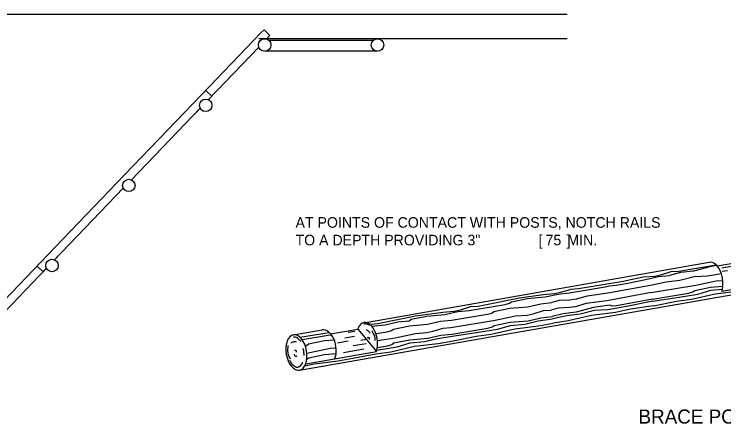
# Model space of a CAD drawing. Extents: x 49991 to 50288, y 49919 to 50011.
# Drawn here: x 50102.33 to 50131.11, y 49960.39 to 49977 of the extents above; entities that cross this region are included whole.
import ezdxf

# ---------------------------------------------------------------- set-up
doc = ezdxf.new("R2010")
doc.units = 0
for name, color, linetype in [('Level 1', 7, 'Continuous'), ('Level 2', 7, 'Continuous'), ('Level 7', 7, 'Continuous')]:
    doc.layers.add(name, color=color, linetype=linetype)

msp = doc.modelspace()

# ---------------------------------------------------------------- linework, layer by layer
at = {"layer": 'Level 1'}
for p, q in [((50059.75292181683, 49976.99558000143), (50124.75625647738, 49976.99558000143)), ((50124.75625647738, 49975.99557998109), (50112.25625622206, 49975.99557998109)), ((50112.25625622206, 49975.99557998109), (50112.25625622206, 49975.99557998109)), ((50116.90350931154, 49975.93557997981), (50112.660963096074, 49975.93557997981)), ((50117.06883965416, 49975.494707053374), (50112.49308956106, 49975.49695705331)), ((50113.90505239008, 49962.567250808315), (50149.87663416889, 49968.84808164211)), ((50116.520059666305, 49964.49143184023), (50130.523789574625, 49966.93785282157)), ((50131.954379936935, 49966.97514372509), (50130.84970517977, 49966.78227097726)), ((50131.96889181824, 49966.86947742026), (50131.02839103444, 49966.70487244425)), ((50131.26102300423, 49966.59721857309), (50131.05133796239, 49966.56090967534)), ((50131.02828853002, 49965.77066362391), (50132.712934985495, 49966.06495613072)), ((50113.663257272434, 49963.995649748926), (50114.82930681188, 49964.199365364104)), ((50115.16749844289, 49964.04250308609), (50116.2666037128, 49964.23451505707)), ((50115.883282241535, 49964.100603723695), (50116.1527901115, 49964.148121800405)), ((50116.2666037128, 49964.23451505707), (50117.02629303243, 49963.32762575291)), ((50115.74198177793, 49963.87829686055), (50116.13803925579, 49963.94777193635)), ((50115.4423207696, 49963.67660187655), (50115.87895074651, 49963.752878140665)), ((50116.076290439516, 49963.56094801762), (50116.604017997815, 49963.65315100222)), ((50116.39043230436, 49963.78782972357), (50116.60856542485, 49963.82629257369)), ((50114.15968473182, 49962.826833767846), (50117.026293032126, 49963.32762575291)), ((50115.691358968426, 49963.28703951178), (50116.51805030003, 49963.43219941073))]:
    msp.add_line(p, q, dxfattribs=at)
for points in [[(50130.8272706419, 49966.807120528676), (50130.59782333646, 49966.77442249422), (50129.88999318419, 49966.58445958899), (50129.35730476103, 49966.51939833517), (50128.9160325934, 49966.409742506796)], [(50129.28732143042, 49966.58514272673), (50130.799775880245, 49966.83498333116)], [(50125.22073166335, 49965.87554302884), (50127.028379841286, 49966.17369169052), (50127.85023236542, 49966.34482402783), (50128.31721149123, 49966.38033114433), (50128.564988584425, 49966.43220022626), (50128.984814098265, 49966.56160314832), (50129.28732143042, 49966.58514272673)], [(50131.01458391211, 49966.47797358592), (50130.45543829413, 49966.37421677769), (50129.90699049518, 49966.344626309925), (50129.335264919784, 49966.19605751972), (50128.782820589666, 49966.127752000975), (50128.20787660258, 49966.01454465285)], [(50124.848838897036, 49965.6991341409), (50126.30784767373, 49965.940086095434), (50126.48360027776, 49965.988928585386), (50126.754183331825, 49966.00861599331), (50127.21653904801, 49966.0930268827), (50127.9397412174, 49966.24376557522), (50128.46297562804, 49966.36315911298), (50128.9160325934, 49966.409742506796)], [(50128.172146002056, 49965.71365178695), (50129.979745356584, 49966.01226816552), (50130.80271834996, 49966.18399027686), (50131.073420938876, 49966.20420989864)], [(50121.1535623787, 49965.164700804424), (50122.823639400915, 49965.49281741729), (50123.78392527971, 49965.63478102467), (50124.25046110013, 49965.67000545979), (50124.49844764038, 49965.72213281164), (50124.91731330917, 49965.85167194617), (50125.22073166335, 49965.87554302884)], [(50128.20787660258, 49966.01454465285), (50126.40589722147, 49965.682472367), (50125.57276864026, 49965.56500930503), (50125.12318792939, 49965.439828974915), (50124.87212800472, 49965.405820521), (50124.43393541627, 49965.38442941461), (50124.14112621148, 49965.304218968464)], [(50128.21819159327, 49965.44919115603), (50129.67683029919, 49965.68915885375), (50129.85258290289, 49965.73800134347), (50129.934602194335, 49965.79928164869), (50130.57850754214, 49965.93127149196), (50131.0735271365, 49965.97332495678)], [(50128.26501835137, 49965.177247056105), (50129.19945831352, 49965.36367799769), (50129.8097608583, 49965.44842497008), (50130.769358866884, 49965.665614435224), (50131.7343230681, 49965.783836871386), (50132.33078448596, 49965.88794281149)], [(50120.781620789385, 49964.988759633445), (50122.24083901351, 49965.229969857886), (50122.41661602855, 49965.278578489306), (50122.49868414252, 49965.33939107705), (50123.14191232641, 49965.47107382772), (50123.872805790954, 49965.532947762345), (50124.3965079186, 49965.65239012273), (50124.848838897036, 49965.6991341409)], [(50128.172146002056, 49965.71365178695), (50126.36998158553, 49965.38108737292), (50125.53729630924, 49965.26390699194), (50125.0874573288, 49965.13893610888), (50124.83618795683, 49965.10466938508), (50124.39862370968, 49965.08405308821), (50124.10570270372, 49965.002648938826)], [(50128.23330024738, 49965.35880611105), (50129.30546187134, 49965.5213153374), (50130.063854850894, 49965.645870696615), (50130.59059366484, 49965.80416432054), (50131.051502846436, 49965.84652030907)], [(50120.07423960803, 49964.59293343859), (50121.532707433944, 49964.83453814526), (50121.7092348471, 49964.8827522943), (50121.790528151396, 49964.94419322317), (50122.43474059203, 49965.07550590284), (50123.165166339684, 49965.1373310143), (50123.6886101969, 49965.2569828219), (50124.14112621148, 49965.304218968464)], [(50128.21819159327, 49965.44919115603), (50126.76421691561, 49965.18039589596), (50126.581947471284, 49965.16680694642), (50126.484955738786, 49965.19687153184), (50125.83405557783, 49965.10244940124), (50125.12645928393, 49964.912510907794), (50124.593278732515, 49964.847634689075), (50124.15219160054, 49964.73847098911)], [(50128.23330024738, 49965.35880611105), (50127.17102958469, 49965.149102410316), (50126.415256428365, 49965.008508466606), (50125.86634091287, 49964.97886917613), (50125.29513187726, 49964.82988149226), (50124.74191273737, 49964.76220431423), (50124.167743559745, 49964.64836862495)], [(50117.086344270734, 49964.45432629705), (50118.61402123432, 49964.77491785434), (50119.716755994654, 49964.92393880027), (50120.18371070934, 49964.959679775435), (50120.43120512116, 49965.01199216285), (50120.85040229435, 49965.14062027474), (50121.1535623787, 49965.164700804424)], [(50118.305351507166, 49964.555331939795), (50118.350357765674, 49964.56806776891), (50118.432192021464, 49964.628855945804), (50119.07521075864, 49964.76028042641), (50119.80561209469, 49964.82233939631), (50120.32949925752, 49964.9422738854), (50120.781620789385, 49964.988759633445)], [(50120.04007278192, 49964.292913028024), (50121.84678552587, 49964.59096404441), (50122.66973410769, 49964.762920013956), (50123.13598724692, 49964.79858775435), (50123.38423205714, 49964.85050565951), (50123.803146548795, 49964.9795770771), (50124.10570270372, 49965.002648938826)], [(50128.26501835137, 49965.177247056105), (50127.32368902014, 49965.036432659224), (50126.71979787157, 49964.90838331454), (50125.74440768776, 49964.788126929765), (50124.796059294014, 49964.57187535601), (50124.19915457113, 49964.46748673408)], [(50120.0859577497, 49964.02772641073), (50121.5436610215, 49964.26759646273), (50121.7202025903, 49964.31793974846), (50121.80100376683, 49964.37956571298), (50122.444982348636, 49964.5108539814), (50123.175505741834, 49964.57174365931), (50123.69967558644, 49964.691234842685), (50124.15219160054, 49964.73847098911)], [(50116.75633539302, 49964.42247860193), (50116.78336922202, 49964.430737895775), (50117.086344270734, 49964.45432629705)], [(50116.82898881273, 49964.35606730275), (50117.374090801, 49964.40185697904), (50117.8976952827, 49964.522234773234), (50118.350357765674, 49964.56806776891)], [(50117.00587118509, 49964.04758093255), (50117.46553814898, 49964.123695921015), (50117.64133957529, 49964.17207069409), (50117.72361713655, 49964.233141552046), (50118.36726421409, 49964.3653408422), (50119.09766555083, 49964.427399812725), (50119.621416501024, 49964.54637445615), (50120.07423960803, 49964.59293343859)], [(50120.1011782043, 49963.938535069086), (50121.171678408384, 49964.10110727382), (50121.93101707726, 49964.223397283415), (50122.457892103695, 49964.38265075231), (50123.04480982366, 49964.43776992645), (50123.58899384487, 49964.56029592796), (50124.167743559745, 49964.64836862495)], [(50120.13242859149, 49963.756927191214), (50121.06598194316, 49963.94279276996), (50121.67778528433, 49964.02675077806), (50122.636817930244, 49964.24482685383), (50123.60248370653, 49964.363122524), (50124.19915457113, 49964.46748673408)], [(50117.07008941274, 49963.76303144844), (50117.78047844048, 49963.880921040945), (50118.60387032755, 49964.053159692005), (50119.07003607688, 49964.08739987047), (50119.3181344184, 49964.14072092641), (50119.73712214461, 49964.26909076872), (50120.04007278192, 49964.292913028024)], [(50113.920332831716, 49963.90107322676), (50115.11500544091, 49964.09820945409)], [(50114.00863900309, 49963.803775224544), (50115.07048511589, 49963.978904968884), (50115.19631263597, 49964.00551472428)], [(50117.0430554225, 49963.38042281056), (50117.10619495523, 49963.38996821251), (50117.86512888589, 49963.513870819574), (50118.391794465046, 49963.67286601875), (50118.97852714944, 49963.72749306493), (50119.522501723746, 49963.84976079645), (50120.1011782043, 49963.938535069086)], [(50117.06577854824, 49963.4903289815), (50117.4779822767, 49963.55832826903), (50117.65324275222, 49963.607355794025), (50117.7355691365, 49963.66795893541), (50118.378821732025, 49963.79940782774), (50119.10940810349, 49963.86195892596), (50119.632925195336, 49963.98090915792), (50120.0859577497, 49964.02772641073)], [(50114.13804767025, 49963.556953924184), (50114.18780141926, 49963.57068988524), (50114.269328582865, 49963.63215522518), (50114.91325834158, 49963.763911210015), (50115.30907517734, 49963.79719095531)], [(50116.06654039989, 49963.047400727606), (50117.000240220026, 49963.231863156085), (50117.61204356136, 49963.31582116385), (50118.57069588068, 49963.53527597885), (50119.53549945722, 49963.65277242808), (50120.13242859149, 49963.756927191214)], [(50114.20475088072, 49963.2608214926), (50114.326326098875, 49963.280894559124), (50115.14934791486, 49963.452148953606), (50115.38833315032, 49963.47047618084)], [(50114.11834303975, 49962.736798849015), (50114.504671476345, 49962.82478967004), (50115.470829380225, 49962.942900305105), (50116.06654039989, 49963.047400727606)], [(50114.20249564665, 49963.00869546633), (50114.28157741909, 49963.06865844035), (50114.92602371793, 49963.19999553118), (50115.389114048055, 49963.23917508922)]]:
    msp.add_lwpolyline(points, dxfattribs=at)
for centre, major_axis, ratio, start_param, end_param in [((50130.64868369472, 49966.22461276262), (-0.12527116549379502, 0.7134132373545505), 0.577493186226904, 3.925707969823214, 6.306125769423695), ((50116.6454763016, 49963.778408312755), (-0.12527116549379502, 0.7134132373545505), 0.577493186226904, 3.9315222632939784, 7.063530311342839), ((50114.96399545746, 49963.48779928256), (-0.12527116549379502, 0.7134132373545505), 0.5774931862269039, 3.9254893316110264, 6.306125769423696), ((50113.78006268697, 49963.28090428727), (-0.12527116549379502, 0.7134132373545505), 0.5774931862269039, 3.9256121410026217, 7.063370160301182), ((50113.779987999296, 49963.28070026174), (-0.12527116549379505, 0.7134132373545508), 0.5774931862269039, 0.7858875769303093, 3.9259797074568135)]:
    msp.add_ellipse(centre, major_axis=major_axis, ratio=ratio, start_param=start_param, end_param=end_param, dxfattribs=at)
for points in [[(50116.73636325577, 49964.38280514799), (50116.712655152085, 49964.406098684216), (50116.64412336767, 49964.428495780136), (50116.605869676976, 49964.43939626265), (50116.55723102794, 49964.43881081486), (50116.512413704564, 49964.431059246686)], [(50116.61030941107, 49964.20889045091), (50116.623104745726, 49964.20407952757), (50116.67759086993, 49964.1780886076), (50116.715377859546, 49964.13995264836), (50116.747901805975, 49964.10694106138), (50116.75815258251, 49964.06309383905)], [(50116.976153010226, 49963.76835586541), (50116.97528055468, 49963.7699196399), (50116.97148449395, 49963.86290399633), (50116.96261635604, 49963.911623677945), (50116.95376771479, 49963.982804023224), (50116.890197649, 49964.064111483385), (50116.86006789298, 49964.133070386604), (50116.84295029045, 49964.163434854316)], [(50113.65888312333, 49963.924255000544), (50113.701496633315, 49963.9168829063), (50113.75538027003, 49963.90572271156), (50113.7862867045, 49963.895000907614), (50113.82082942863, 49963.87662085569), (50113.84397217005, 49963.854213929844), (50113.86696454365, 49963.828718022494), (50113.90216247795, 49963.79953166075), (50113.91348778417, 49963.78842071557), (50113.92902499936, 49963.7664019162), (50113.944383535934, 49963.73703586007), (50113.9481277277, 49963.72607918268)], [(50116.66522936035, 49963.890894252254), (50116.667431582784, 49963.89279800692), (50116.66857570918, 49963.89374080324), (50116.66915922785, 49963.894209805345), (50116.669750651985, 49963.894677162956), (50116.671508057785, 49963.89590022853), (50116.67333358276, 49963.89688544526), (50116.67715570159, 49963.89821504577), (50116.6852511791, 49963.8988199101), (50116.69350444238, 49963.8976551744), (50116.69752379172, 49963.89677277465), (50116.70138284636, 49963.89588425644), (50116.70397123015, 49963.89527555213), (50116.70654358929, 49963.89458904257), (50116.711611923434, 49963.89283421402), (50116.71653123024, 49963.890322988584), (50116.71891730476, 49963.88869098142), (50116.72008885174, 49963.887764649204), (50116.721244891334, 49963.886758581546), (50116.72419164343, 49963.88391728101), (50116.7268616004, 49963.88100058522), (50116.73127161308, 49963.874894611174), (50116.734275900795, 49963.8683478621), (50116.735188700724, 49963.86488019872), (50116.735675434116, 49963.861267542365), (50116.736130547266, 49963.852717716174), (50116.7362863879, 49963.8442068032), (50116.73617975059, 49963.83571409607), (50116.73584743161, 49963.8272188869), (50116.73559749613, 49963.82203445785), (50116.735351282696, 49963.816850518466), (50116.73507243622, 49963.81166884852), (50116.73472460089, 49963.80649122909)], [(50113.438375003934, 49963.570689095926), (50113.437866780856, 49963.544130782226), (50113.437459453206, 49963.53087903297), (50113.43633831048, 49963.517684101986), (50113.430993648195, 49963.476760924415), (50113.42525236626, 49963.43591223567), (50113.42167906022, 49963.418087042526), (50113.41719125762, 49963.40036694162), (50113.413395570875, 49963.382576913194), (50113.41225933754, 49963.373600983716), (50113.411969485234, 49963.3690832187), (50113.411898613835, 49963.36454194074), (50113.413857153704, 49963.348373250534), (50113.418253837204, 49963.33255830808), (50113.423378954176, 49963.31683086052), (50113.42568039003, 49963.30891674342), (50113.427522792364, 49963.30092465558), (50113.43293233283, 49963.27146345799), (50113.438400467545, 49963.24201284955), (50113.44797010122, 49963.19640953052), (50113.45367052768, 49963.173803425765), (50113.45688328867, 49963.16257308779), (50113.46038866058, 49963.15140030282), (50113.47326220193, 49963.12199005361), (50113.49018445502, 49963.09469968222), (50113.540617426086, 49963.02147716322)], [(50113.56025208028, 49963.671386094), (50113.57140231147, 49963.67929418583), (50113.62344407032, 49963.70988701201), (50113.67619892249, 49963.71984359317), (50113.72176114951, 49963.728308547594), (50113.763830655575, 49963.712251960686)], [(50113.700050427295, 49963.37846267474), (50113.70038819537, 49963.37873358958), (50113.70097961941, 49963.37920094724), (50113.702737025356, 49963.380424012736), (50113.70456255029, 49963.3814092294), (50113.70838466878, 49963.38273883), (50113.71036747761, 49963.38311918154), (50113.71238374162, 49963.38335585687), (50113.716480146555, 49963.38334369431), (50113.71857742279, 49963.383139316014), (50113.720645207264, 49963.38288801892), (50113.72269377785, 49963.382573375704), (50113.72473340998, 49963.382178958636), (50113.728752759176, 49963.381296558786), (50113.73261181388, 49963.380408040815), (50113.735200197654, 49963.379799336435), (50113.737772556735, 49963.37911282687), (50113.74284089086, 49963.37735799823), (50113.747760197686, 49963.37484677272), (50113.75014627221, 49963.373214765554), (50113.751317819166, 49963.37228843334), (50113.75247385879, 49963.37128236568), (50113.75542061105, 49963.36844106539), (50113.75809056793, 49963.365524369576), (50113.76041852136, 49963.36257104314), (50113.761486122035, 49963.361021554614), (50113.76250058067, 49963.35941839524), (50113.764186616, 49963.35622407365), (50113.76550486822, 49963.352871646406), (50113.766417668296, 49963.34940398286), (50113.76690440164, 49963.345791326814), (50113.767359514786, 49963.33724150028), (50113.76751535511, 49963.32873058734), (50113.76740871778, 49963.32023788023), (50113.76707639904, 49963.31174267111), (50113.7668264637, 49963.30655824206), (50113.76658025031, 49963.30137430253), (50113.76644738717, 49963.298784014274)], [(50114.0934931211, 49963.15564687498), (50114.09704926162, 49963.18809149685), (50114.08908556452, 49963.2221923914), (50114.078343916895, 49963.30473239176), (50114.076717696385, 49963.326600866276), (50114.07207225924, 49963.390089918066), (50114.04554162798, 49963.43337756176)], [(50113.5064989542, 49962.973746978), (50113.53547747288, 49962.91128728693), (50113.541642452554, 49962.89873559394), (50113.548202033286, 49962.88639133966), (50113.55506224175, 49962.874188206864), (50113.56212910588, 49962.862059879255), (50113.572170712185, 49962.84609112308), (50113.5831514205, 49962.83081216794), (50113.59516146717, 49962.81628607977), (50113.60158069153, 49962.80932507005), (50113.60829108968, 49962.802575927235), (50113.63478239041, 49962.77946430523), (50113.66278602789, 49962.75838261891), (50113.680570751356, 49962.74578654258), (50113.6985286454, 49962.7336292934), (50113.716770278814, 49962.72185494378), (50113.7354062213, 49962.7104075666), (50113.7465729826, 49962.7042151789), (50113.757988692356, 49962.698853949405), (50113.76987444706, 49962.69417335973), (50113.77606268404, 49962.692041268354), (50113.78245134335, 49962.69002289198), (50113.79346845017, 49962.68725625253), (50113.80440243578, 49962.685678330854), (50113.81521503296, 49962.68533714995), (50113.82056385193, 49962.68564534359), (50113.82586797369, 49962.68628073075), (50113.8400371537, 49962.689173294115), (50113.85405019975, 49962.693441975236), (50113.87461088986, 49962.70211620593), (50113.88130411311, 49962.70554264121), (50113.89344625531, 49962.71219183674), (50113.905141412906, 49962.71914158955), (50113.92714960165, 49962.73515094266), (50113.936379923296, 49962.74375636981), (50113.94538906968, 49962.752542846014), (50113.96293282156, 49962.77056468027), (50113.970294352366, 49962.77838128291), (50113.977808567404, 49962.786122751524), (50113.99254267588, 49962.801813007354), (50114.00563039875, 49962.81850088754), (50114.01556698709, 49962.837051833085), (50114.026626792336, 49962.86581409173), (50114.03700140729, 49962.89402979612)], [(50113.79991110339, 49963.14002618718), (50113.79844174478, 49963.137513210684), (50113.79766342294, 49963.13625142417), (50113.79726264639, 49963.1356190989), (50113.7968538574, 49963.13498577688), (50113.795585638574, 49963.13326067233), (50113.79417613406, 49963.131738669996), (50113.7909882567, 49963.12924590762), (50113.783521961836, 49963.1260588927), (50113.77533481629, 49963.12449568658), (50113.77124587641, 49963.124032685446), (50113.767306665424, 49963.12362724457), (50113.76466040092, 49963.1233673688), (50113.762004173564, 49963.12318630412), (50113.75664069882, 49963.12321019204), (50113.75117397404, 49963.12399807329), (50113.74838868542, 49963.12477200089), (50113.74698074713, 49963.1252703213), (50113.745561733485, 49963.125849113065), (50113.74185525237, 49963.127586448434), (50113.73838638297, 49963.12948453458), (50113.732240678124, 49963.133839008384), (50113.72728301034, 49963.139064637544), (50113.72529918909, 49963.14205166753), (50113.72367177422, 49963.14531352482), (50113.72047974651, 49963.153258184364), (50113.717583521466, 49963.16126267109), (50113.71494158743, 49963.169334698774), (50113.712512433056, 49963.17748198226), (50113.71107458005, 49963.182469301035), (50113.70963336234, 49963.18745495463), (50113.70822376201, 49963.192448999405), (50113.706880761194, 49963.19746149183)]]:
    msp.add_spline(points, degree=3, dxfattribs=at)
at = {"layer": 'Level 7'}
for p, q in [((50112.3534497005, 49976.2474798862), (50109.92896457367, 49973.724469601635)), ((50112.46618710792, 49976.36479866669), (50112.3534497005, 49976.2474798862)), ((50112.70839999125, 49976.13204435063), (50112.46618710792, 49976.36479866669)), ((50112.56982239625, 49975.987835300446), (50112.70839999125, 49976.13204435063)), ((50112.256892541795, 49975.66218874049), (50110.20648849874, 49973.52846128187)), ((50109.92896457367, 49973.724469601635), (50106.81096868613, 49970.47976597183)), ((50110.34506609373, 49973.672670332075), (50110.1028532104, 49973.90542464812)), ((50110.20648849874, 49973.52846128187), (50110.34506609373, 49973.672670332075)), ((50109.877816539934, 49973.186432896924), (50107.0884926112, 49970.28375765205)), ((50109.877816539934, 49973.186432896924), (50109.73923894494, 49973.04222384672)), ((50106.81096868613, 49970.47976597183), (50103.69297279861, 49967.235062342)), ((50106.75982065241, 49969.9417292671), (50103.970496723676, 49967.03905402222)), ((50103.69297279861, 49967.235062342), (50100.57497691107, 49963.99035871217)), ((50103.970496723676, 49967.03905402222), (50104.10907431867, 49967.183263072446)), ((50103.5032471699, 49966.55281658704), (50103.26103428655, 49966.78557090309)), ((50103.6418247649, 49966.69702563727), (50100.85250083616, 49963.79435039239)), ((50103.6418247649, 49966.69702563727), (50103.5032471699, 49966.55281658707))]:
    msp.add_line(p, q, dxfattribs=at)
for centre, radius in [((50112.49308956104, 49975.7483935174), 0.2514364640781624), ((50117.06883965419, 49975.74614351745), 0.2514364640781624), ((50110.102341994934, 49973.29960805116), 0.25143646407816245), ((50106.98434610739, 49970.05490442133), 0.25143646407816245), ((50103.86635021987, 49966.81020079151), 0.25143646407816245)]:
    msp.add_circle(centre, radius, dxfattribs=at)

# ---------------------------------------------------------------- texts
at = {"layer": 'Level 2'}
for s, height, p in [('AT POINTS OF CONTACT WITH POSTS, NOTCH RAILS', 0.4285227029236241, (50113.744438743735, 49968.340102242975)), ('TO A DEPTH PROVIDING 3" ', 0.4285227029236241, (50113.744438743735, 49967.6258977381)), ('[', 0.4285227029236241, (50123.60046091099, 49967.6258977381)), ('75', 0.4285227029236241, (50123.88389324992, 49967.6258977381)), (']', 0.4285227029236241, (50124.74093865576, 49967.6258977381)), ('  MIN. ', 0.4285227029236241, (50124.4507579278, 49967.6258977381)), ('BRACE POLE NOTCHING', 0.5713636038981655, (50127.65499290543, 49960.40062793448))]:
    msp.add_text(s, height=height, dxfattribs=at).set_placement(p)

doc.saveas('drawing.dxf')
